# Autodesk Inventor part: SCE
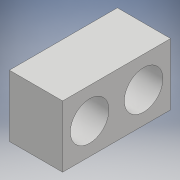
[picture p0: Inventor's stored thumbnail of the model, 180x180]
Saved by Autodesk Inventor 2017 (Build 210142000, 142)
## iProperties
Part Number: SCE
Material: Genérico
Document SubType Name: Modeling
Designer: Diego
Density: 1 g/cm^3
Appearance: Valor por defecto
Author: Diego
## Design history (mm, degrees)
derived "Lubina.ipt"
feature "Sólido19::Lubina.ipt" dims "d0" = 10
tag "OperaciónIdentificador1"
node "Sólido1"
